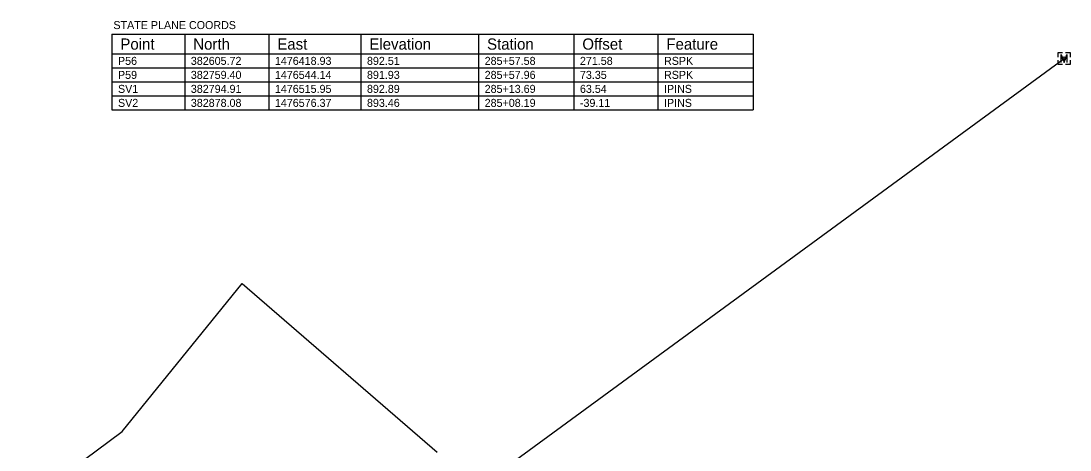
# Model space of a CAD drawing. Extents: x 1474076 to 1484331, y 375886 to 383395.
# Drawn here: x 1476489 to 1477145, y 382992 to 383260 of the extents above; entities that cross this region are included whole.
import ezdxf

# ---------------------------------------------------------------- set-up
doc = ezdxf.new("R2010")
doc.units = 0
for name, color, linetype in [('DV_X_Property_Line', 7, 'Continuous'), ('PM_X_Channelizing_Line', 7, 'Continuous'), ('SV_X_Mon_Cells_Found', 7, 'Continuous'), ('SV_X_Shot_Marker', 7, 'Continuous'), ('SV_X_Text', 7, 'Continuous'), ('SV_X_Text_Elevation', 7, 'Continuous'), ('VG_X_Cells', 7, 'Continuous')]:
    doc.layers.add(name, color=color, linetype=linetype)

msp = doc.modelspace()

# ---------------------------------------------------------------- linework, layer by layer
at = {"layer": 'DV_X_Property_Line'}
msp.add_lwpolyline([(1476489.36, 382956.28), (1476552.48, 383003.4), (1476627.56, 383095.93), (1476749.26, 382990.49)], dxfattribs=at)
at = {"layer": 'PM_X_Channelizing_Line'}
msp.add_line((1476728.51, 382934.52), (1477140.75, 383236.47), dxfattribs=at)
msp.add_circle((1477140.75, 383236.47), 1, dxfattribs=at)
at = {"layer": 'SV_X_Mon_Cells_Found'}
msp.add_line((1477140.75, 383236.47), (1477140.75, 383236.47), dxfattribs=at)
msp.add_line((1477140.75, 383236.47), (1477140.75, 383236.47), dxfattribs=at)
for points in [[(1477137, 383237.42), (1477137, 383240.22), (1477139.81, 383240.22)], [(1477138.9, 383233.97), (1477138.9, 383238.97), (1477140.75, 383233.97), (1477142.6, 383238.97), (1477142.6, 383233.97)], [(1477140.68, 383236.49), (1477140.68, 383236.55), (1477140.73, 383236.55)], [(1477140.73, 383236.39), (1477140.68, 383236.39), (1477140.68, 383236.45)], [(1477140.71, 383236.42), (1477140.71, 383236.52), (1477140.75, 383236.42), (1477140.79, 383236.52), (1477140.79, 383236.42)], [(1477140.77, 383236.55), (1477140.83, 383236.55), (1477140.83, 383236.49)], [(1477140.83, 383236.45), (1477140.83, 383236.39), (1477140.77, 383236.39)], [(1477141.64, 383240.22), (1477144.51, 383240.22), (1477144.51, 383237.42)], [(1477139.81, 383232.72), (1477137, 383232.72), (1477137, 383235.52)], [(1477144.51, 383235.52), (1477144.51, 383232.72), (1477141.64, 383232.72)]]:
    msp.add_lwpolyline(points, dxfattribs=at)
at = {"layer": 'VG_X_Cells'}
for p, q in [((1476546.19, 383251.67), (1476946.69, 383251.67)), ((1476546.19, 383251.67), (1476546.19, 383204.42)), ((1476591.69, 383251.67), (1476591.69, 383204.42)), ((1476644.19, 383251.67), (1476644.19, 383204.42)), ((1476701.69, 383251.67), (1476701.69, 383204.42)), ((1476775.19, 383251.67), (1476775.19, 383204.42)), ((1476834.69, 383251.67), (1476834.69, 383204.42)), ((1476887.19, 383251.67), (1476887.19, 383204.42)), ((1476946.69, 383251.67), (1476946.69, 383204.42)), ((1476946.69, 383251.67), (1476946.69, 383204.42)), ((1476546.19, 383239.42), (1476946.69, 383239.42)), ((1476546.19, 383230.67), (1476946.69, 383230.67)), ((1476546.19, 383230.67), (1476946.69, 383230.67)), ((1476546.19, 383230.67), (1476946.69, 383230.67)), ((1476546.19, 383230.67), (1476946.69, 383230.67)), ((1476546.19, 383230.67), (1476946.69, 383230.67)), ((1476546.19, 383230.67), (1476946.69, 383230.67)), ((1476546.19, 383230.67), (1476946.69, 383230.67)), ((1476546.19, 383221.92), (1476946.69, 383221.92)), ((1476546.19, 383221.92), (1476946.69, 383221.92)), ((1476546.19, 383221.92), (1476946.69, 383221.92)), ((1476546.19, 383221.92), (1476946.69, 383221.92)), ((1476546.19, 383221.92), (1476946.69, 383221.92)), ((1476546.19, 383221.92), (1476946.69, 383221.92)), ((1476546.19, 383221.92), (1476946.69, 383221.92)), ((1476546.19, 383213.17), (1476946.69, 383213.17)), ((1476546.19, 383213.17), (1476946.69, 383213.17)), ((1476546.19, 383213.17), (1476946.69, 383213.17)), ((1476546.19, 383213.17), (1476946.69, 383213.17)), ((1476546.19, 383213.17), (1476946.69, 383213.17)), ((1476546.19, 383213.17), (1476946.69, 383213.17)), ((1476546.19, 383213.17), (1476946.69, 383213.17)), ((1476546.19, 383204.42), (1476946.69, 383204.42)), ((1476546.19, 383204.42), (1476946.69, 383204.42)), ((1476546.19, 383204.42), (1476946.69, 383204.42)), ((1476546.19, 383204.42), (1476946.69, 383204.42)), ((1476546.19, 383204.42), (1476946.69, 383204.42)), ((1476546.19, 383204.42), (1476946.69, 383204.42)), ((1476546.19, 383204.42), (1476946.69, 383204.42))]:
    msp.add_line(p, q, dxfattribs=at)

# ---------------------------------------------------------------- texts
at = {"layer": 'SV_X_Shot_Marker'}
msp.add_text('55', height=0.06, dxfattribs=at).set_placement((1477140.67, 383236.47))
at = {"layer": 'SV_X_Text'}
msp.add_text('STATE PLANE COORDS', height=5, dxfattribs=at).set_placement((1476547.08, 383254.92))
at = {"layer": 'SV_X_Text_Elevation'}
msp.add_text('840.00', height=0.06, dxfattribs=at).set_placement((1477140.45, 383236.41))
at = {"layer": 'VG_X_Cells'}
for s, height, p in [('Point', 7, (1476551.44, 383242.05)), ('North', 7, (1476596.94, 383242.05)), ('East', 7, (1476649.44, 383242.05)), ('Elevation', 7, (1476706.94, 383242.05)), ('Station', 7, (1476780.44, 383242.05)), ('Offset', 7, (1476839.94, 383242.05)), ('Feature', 7, (1476892.44, 383242.05)), ('P56', 5, (1476549.94, 383232.55)), ('382605.72', 5, (1476595.44, 383232.55)), ('1476418.93', 5, (1476647.94, 383232.55)), ('892.51', 5, (1476705.44, 383232.55)), ('285+57.58', 5, (1476778.94, 383232.55)), ('271.58', 5, (1476838.44, 383232.55)), ('RSPK', 5, (1476890.94, 383232.55)), ('P59', 5, (1476549.94, 383223.8)), ('382759.40', 5, (1476595.44, 383223.8)), ('1476544.14', 5, (1476647.94, 383223.8)), ('891.93', 5, (1476705.44, 383223.8)), ('285+57.96', 5, (1476778.94, 383223.8)), ('73.35', 5, (1476838.44, 383223.8)), ('RSPK', 5, (1476890.94, 383223.8)), ('SV1', 5, (1476549.94, 383215.05)), ('382794.91', 5, (1476595.44, 383215.05)), ('1476515.95', 5, (1476647.94, 383215.05)), ('892.89', 5, (1476705.44, 383215.05)), ('285+13.69', 5, (1476778.94, 383215.05)), ('63.54', 5, (1476838.44, 383215.05)), ('IPINS', 5, (1476890.94, 383215.05)), ('SV2', 5, (1476549.94, 383206.3)), ('382878.08', 5, (1476595.44, 383206.3)), ('1476576.37', 5, (1476647.94, 383206.3)), ('893.46', 5, (1476705.44, 383206.3)), ('285+08.19', 5, (1476778.94, 383206.3)), ('-39.11', 5, (1476838.44, 383206.3)), ('IPINS', 5, (1476890.94, 383206.3))]:
    msp.add_text(s, height=height, dxfattribs=at).set_placement(p)

doc.saveas('drawing.dxf')
